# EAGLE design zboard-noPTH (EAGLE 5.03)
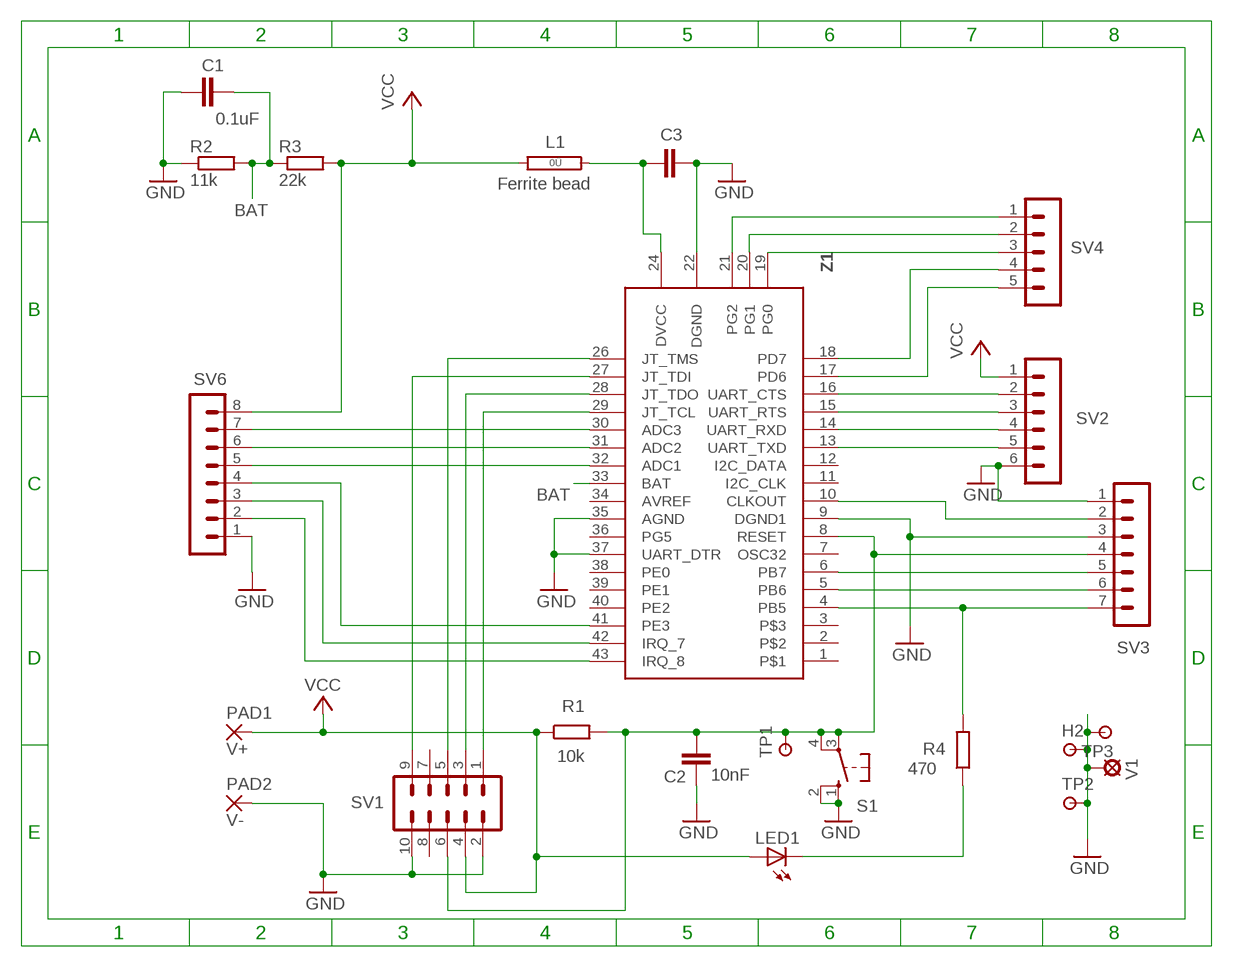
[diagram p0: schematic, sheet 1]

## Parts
C1  0.1uF  C5P  [C050-030-075]
C2  10nF  C5P  [C050-030-075]
C3  10uF 10V ceramic  CSMT0805  [C0805]
H2  HOLE/SMALL  [1,6/0,8@1]
L1  Ferrite bead  0R  [0R/10]
LED1  3mm red LED  LED-3MM3MM  [HLMP-D105]
PAD1  V+  TERMINAL-PAD  [2,54/1,1]
PAD2  V-  TERMINAL-PAD  [2,54/1,1]
R1  10k  R  [0207/10]
R2  11k  R  [0207/10]
R3  22k  R  [0207/10]
R4  470  R  [0207/10]
S1  BW-1000 PCB pushbutton  10-XX  [B3F-10XX]
SV1  10 way IDC male header  ML10  [ML10]
SV2  6 way pin header  MA06-1  [MA06-1]
SV3  7 way pin header  MA07-1  [MA07-1]
SV4  5 way pin header  MA05-1  [MA05-1]
SV6  6 way pin header  MA08-1  [MA08-1]
TP1  PAD-TESTPOINT  [1,6/0,8]
TP2  PAD-TESTPOINT  [1,6/0,8]
TP3  PAD-TESTPOINT  [1,6/0,8]
V1  HOLE/VIA  [LSP10]
Z1  ZDM-A1281-A2N  [ZIGSMD]

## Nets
BAT: C1.2 R2.2 R3.1 Z1.33(BAT)
GND: C1.1 C2.1 C3.2 H2.1(P) PAD2.1(P) R2.1 S1.1(S) S1.2(S1) SV1.2 SV1.10 SV2.6 SV3.1 SV3.3 SV6.1 TP2.1(P) TP3.1(P) V1.MP Z1.9(DGND1) Z1.22(DGND) Z1.35(AGND) Z1.37(UART_DTR)
N$1: SV4.4 Z1.18(PD7)
N$2: SV6.4 Z1.41(PE3)
N$3: SV2.2 Z1.16(UART_CTS)
N$4: SV6.7 Z1.30(ADC3)
N$5: SV6.6 Z1.31(ADC2)
N$7: SV6.5 Z1.32(ADC1)
N$8: SV4.5 Z1.17(PD6)
N$9: SV1.5 Z1.26(JT_TMS)
N$10: SV1.1 Z1.29(JT_TCL)
N$11: SV1.3 Z1.28(JT_TDO)
N$12: SV6.3 Z1.42(IRQ_7)
N$13: C2.2 R1.2 S1.3(P) S1.4(P1) SV1.6 SV3.4 TP1.1(P) Z1.8(RESET)
N$14: SV6.2 Z1.43(IRQ_8)
N$15: SV2.3 Z1.15(UART_RTS)
N$16: SV2.4 Z1.14(UART_RXD)
N$17: SV2.5 Z1.13(UART_TXD)
N$18: SV3.5 Z1.6(PB7)
N$19: SV3.6 Z1.5(PB6)
N$20: SV3.2 Z1.10(CLKOUT)
N$24: SV4.3 Z1.19(PG0)
N$25: SV4.2 Z1.20(PG1)
N$28: R4.2 SV3.7 Z1.4(PB5)
N$29: SV4.1 Z1.21(PG2)
N$30: LED1.K(C) R4.1
N$31: SV1.9 Z1.27(JT_TDI)
N$33 [supply]: C3.1 L1.1 Z1.24(DVCC)
VCC: L1.2 LED1.A PAD1.1(P) R1.1 R3.2 SV1.4 SV2.1 SV6.8
Unconnected: SV1.7 SV1.8 Z1.1 Z1.2 Z1.3 Z1.7(OSC32) Z1.11(I2C_CLK) Z1.12(I2C_DATA) Z1.34(AVREF) Z1.36(PG5) Z1.38(PE0) Z1.39(PE1) Z1.40(PE2)

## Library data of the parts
C1-C3 = ee2parts:C: Capacitor
H2 = ee2parts:HOLE/SMALL: SMALL THROUGH-HOLE PAD/TESTPOINT
L1 = jumper:0R: Bridge 0R 10mm
LED1 = ee2parts:LED-3MM: LED
PAD1 PAD2 = ee2parts:TERMINAL-PAD: LARGE THROUGH-HOLE PAD
R1-R4 = ee2parts:R: Resistor
S1 = switch-omron:10-XX: OMRON SWITCH
SV1 = con-harting-ml:ML10: HARTING
SV2 = con-lstb:MA06-1: PIN HEADER
SV3 = con-lstb:MA07-1: PIN HEADER
SV4 = con-lstb:MA05-1: PIN HEADER
SV6 = con-lstb:MA08-1: PIN HEADER
TP1-TP3 = ee2parts:PAD-TESTPOINT: SMALL THROUGH-HOLE PAD/TESTPOINT
V1 = ee2parts:HOLE/VIA: FIXED VIA
Z1 = ee2parts:ZDM-A1281-A2

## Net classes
1 supply: width 0.635 mm

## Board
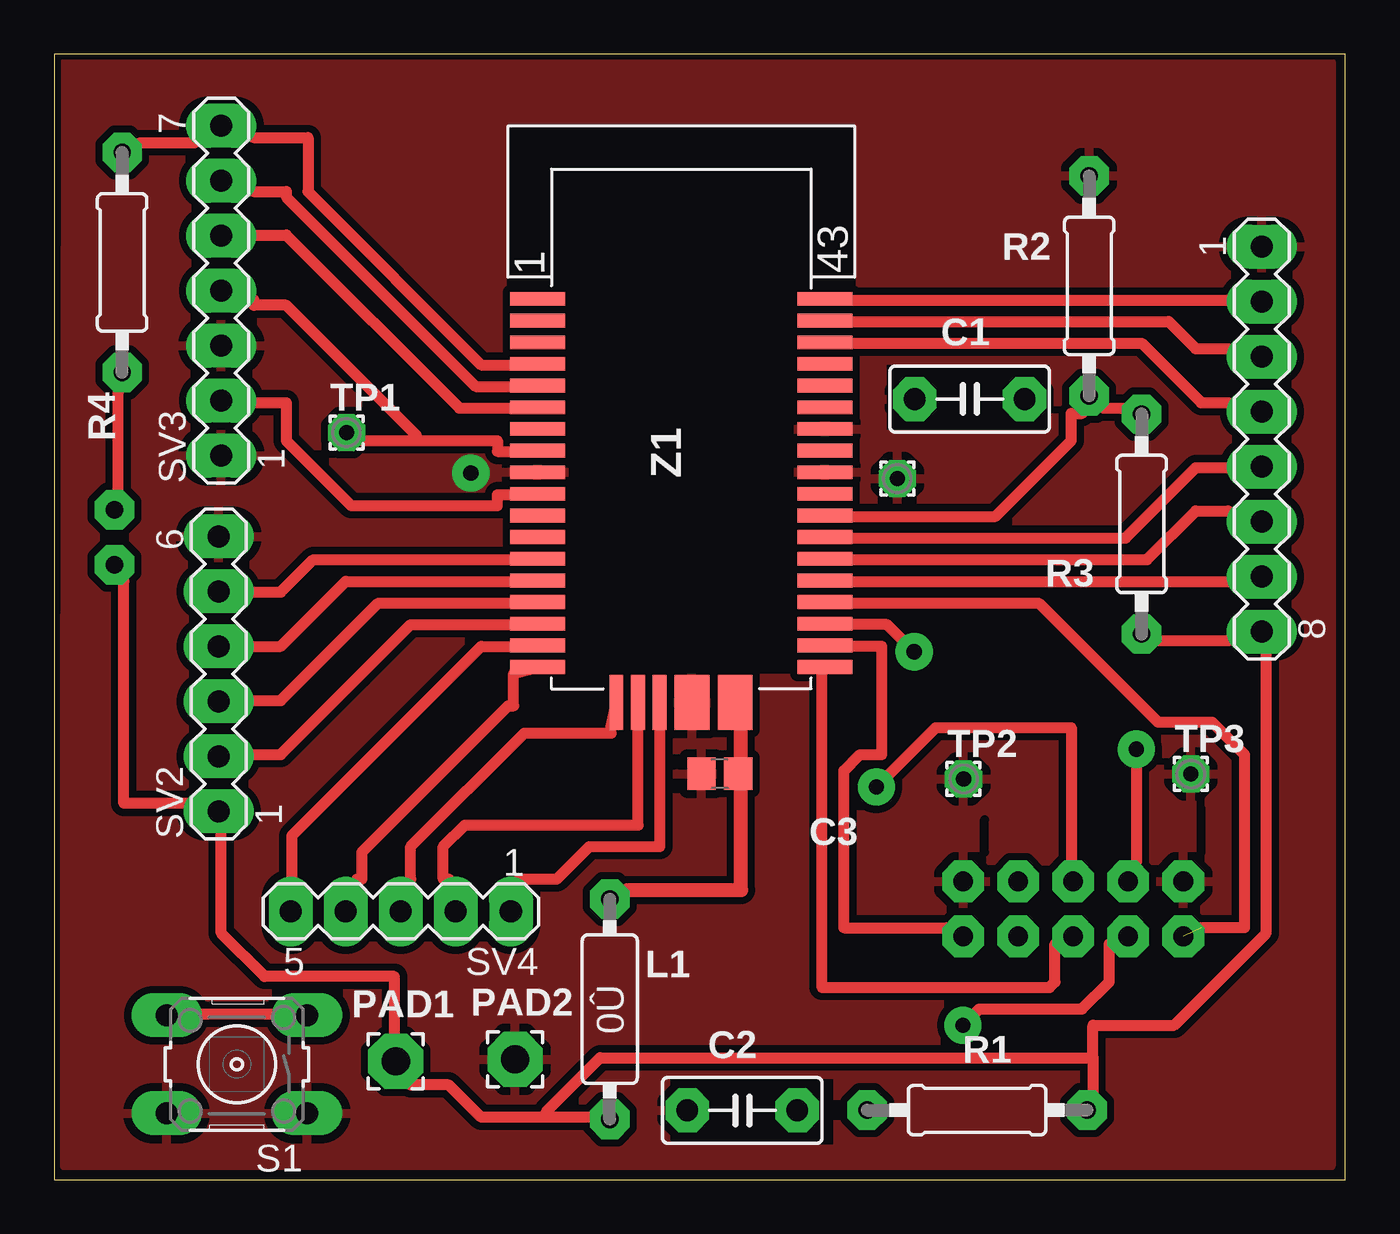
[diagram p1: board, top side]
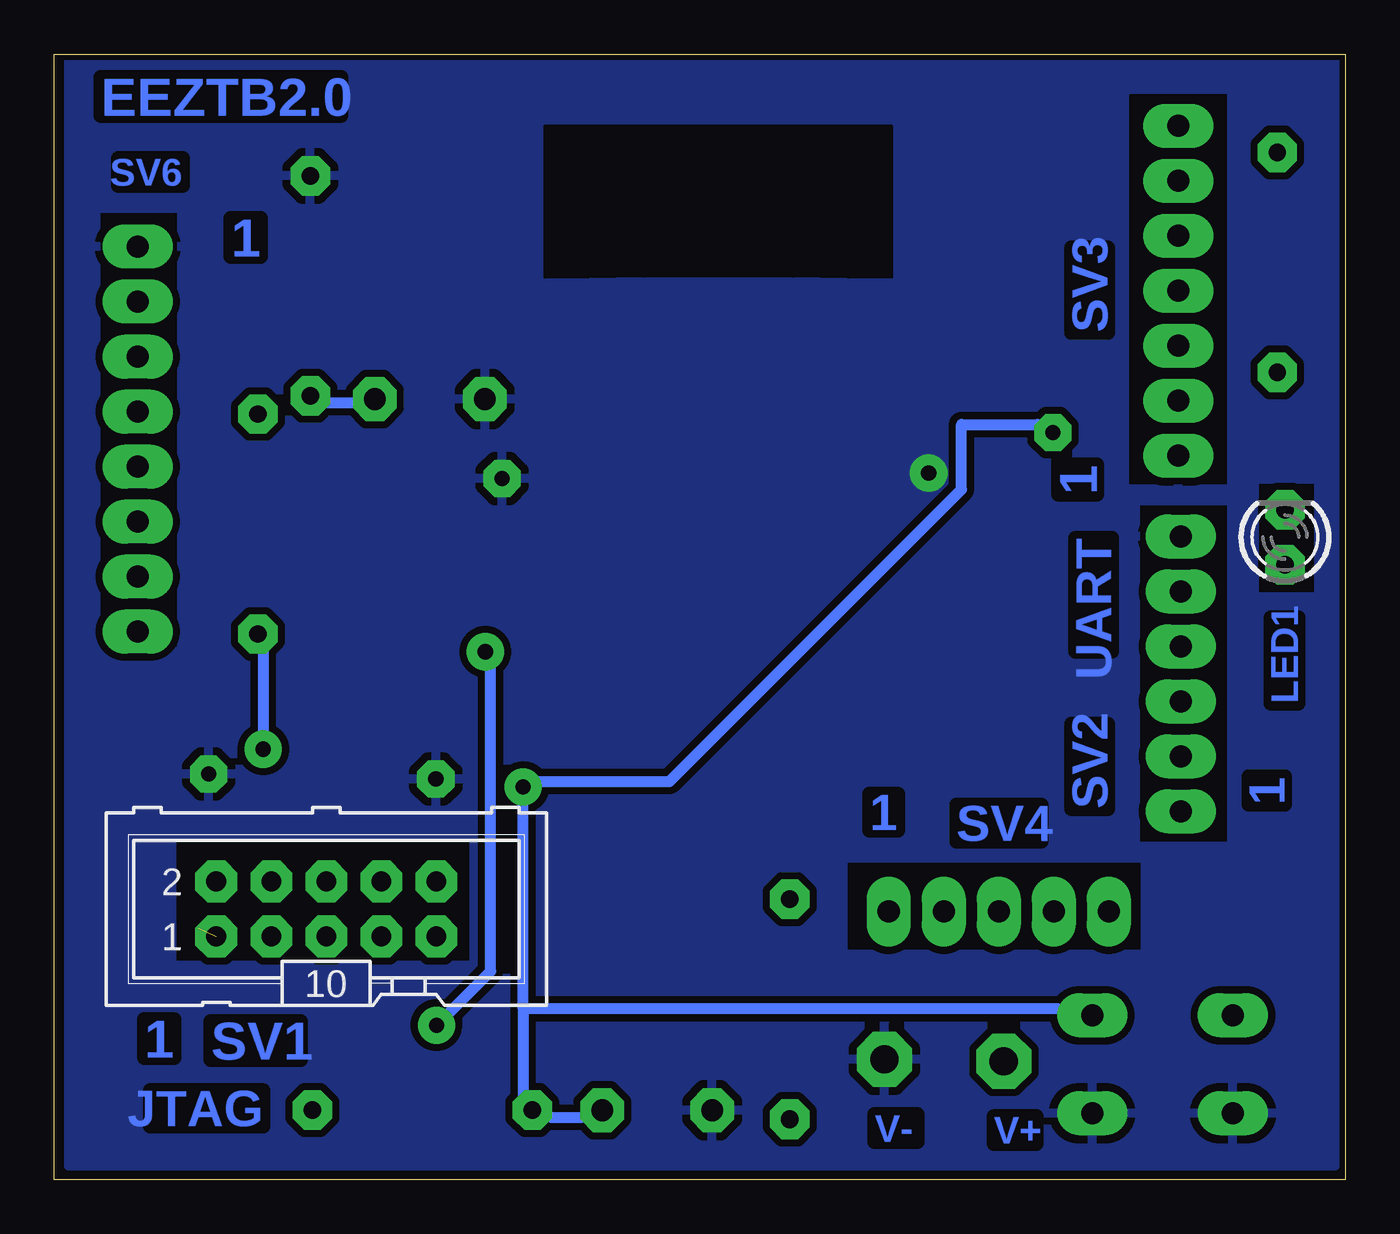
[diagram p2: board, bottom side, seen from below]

Size 59.63 x 51.98 mm. Coordinates in mm from the lower left corner, seen from the top.
Outline: 0,0 59.63,0 59.63,51.98 0,51.98 0,0
Copper layers (1*16): Top 0.035mm / dielectric 1.5mm / Bottom 0.035mm
Design rules "zigbit_rules *": minimum track width 20mil, minimum drill 0.7mm, track to track 13mil, track to pad 13mil, pad to pad 13mil, via to via 13mil, smd to smd 0mil, copper to edge 10mil, drill to drill 10mil, minimum pad ring 20mil, minimum via ring 20mil, stop-mask expansion 0mil, vias tented up to drill 0mil, thermal gap 15mil
tRestrict: area 38.5,34.6 to 46,37.6; area 28.5,1.6 to 36,4.6; 2 lines
bRestrict: area 54,24.6 to 57.5,44.6; area 5.5,32.1 to 10,50.1; area 40.5,10.1 to 54,15.6; area 1.5,27.1 to 4,32.1; area 5.5,15.6 to 9.5,31.1; area 9.5,10.6 to 23,14.6
vRestrict: area 37,8.1 to 57,17.1

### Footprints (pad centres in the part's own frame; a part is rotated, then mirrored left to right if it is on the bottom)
C050-030-075 = drill 1 octagon: 1 -2.54,0; 2 2.54,0
C0805 = smd 1.3 x 1.5: 1 -0.85,0; 2 0.85,0
1,6/0,8@1 = drill 0.7 pad 1.6 octagon: 1 0,0
0R/10 = drill 0.813 pad 1.6 octagon: 1 -5.08,0; 2 5.08,0
HLMP-D105 = drill 0.8 octagon: A -1.27,0; K 1.27,0
2,54/1,1 = drill 1.3 pad 2.54 octagon: 1 0,0
0207/10 = drill 0.8 octagon: 1 -5.08,0; 2 5.08,0
B3F-10XX = drill 1.016 long: 1 -3.251,2.261; 2 3.251,2.261; 3 -3.251,-2.261; 4 3.251,-2.261
ML10 = drill 0.914 octagon: 1 -5.08,-1.27; 2 -5.08,1.27; 3 -2.54,-1.27; 4 -2.54,1.27; 5 0,-1.27; 6 0,1.27; 7 2.54,-1.27; 8 2.54,1.27; 9 5.08,-1.27; 10 5.08,1.27
MA06-1 = drill 1.016 long: 1 -6.35,0; 2 -3.81,0; 3 -1.27,0; 4 1.27,0; 5 3.81,0; 6 6.35,0
MA07-1 = drill 1.016 long: 1 -7.62,0; 2 -5.08,0; 3 -2.54,0; 4 0,0; 5 2.54,0; 6 5.08,0; 7 7.62,0
MA05-1 = drill 1.016 long: 1 -5.08,0; 2 -2.54,0; 3 0,0; 4 2.54,0; 5 5.08,0
MA08-1 = drill 1.016 long: 1 -8.89,0; 2 -6.35,0; 3 -3.81,0; 4 -1.27,0; 5 1.27,0; 6 3.81,0; 7 6.35,0; 8 8.89,0
1,6/0,8 = drill 0.7 pad 1.6 octagon: 1 0,0
LSP10 = drill 0.7 pad 1.016 round: MP 0,0
ZIGSMD = smd 0.635 x 2.54: 1 7,6.635; 2 6,6.635; 3 5,6.635; 4 4,6.635; 5 3,6.635; 6 2,6.635; 7 1,6.635; 8 0,6.635; 9 -1,6.635; 10 -2,6.635; 11 -3,6.635; 12 -4,6.635; 13 -5,6.635; 14 -6,6.635; 15 -7,6.635; 16 -8,6.635; 17 -9,6.635; 18 -10,6.635; 26 -10,-6.635; 27 -9,-6.635; 28 -8,-6.635; 29 -7,-6.635; 30 -6,-6.635; 31 -5,-6.635; 32 -4,-6.635; 33 -3,-6.635; 34 -2,-6.635; 35 -1,-6.635; 36 0,-6.635; 37 1,-6.635; 38 2,-6.635; 39 3,-6.635; 40 4,-6.635; 41 5,-6.635; 42 6,-6.635; 43 7,-6.635 | smd 2.54 x 0.635: 19 -11.635,3; 20 -11.635,2; 21 -11.635,1 | smd 2.54 x 1.6: 22 -11.635,-0.5; 24 -11.635,-2.5

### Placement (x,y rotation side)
C1  42.28,36.05 0 top
C2  31.78,3.2 0 top
C3  30.74,18.75 180 top
H2  38.94,32.39 0 top
L1  25.66,7.87 270 top
LED1  2.79,29.67 90 bottom
PAD1  15.78,5.47 0 top
PAD2  21.28,5.55 0 top
R1  42.62,3.21 180 top
R2  47.8,41.28 270 top
R3  50.22,30.28 270 top
R4  3.14,42.36 90 top
S1  8.44,5.33 180 top
SV1  47.06,12.5 0 bottom
SV2  7.6,23.36 90 top
SV3  7.72,41.05 90 top
SV4  16.01,12.38 180 top
SV6  55.77,34.2 270 top
TP1  13.5,34.5 0 top
TP2  42,18.5 0 top
TP3  52.5,18.73 0 top
V1  19.24,32.63 0 top
Z1  28.96,33.67 90 top

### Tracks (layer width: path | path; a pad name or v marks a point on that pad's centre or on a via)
BAT
  Top 0.508: Z1.33 36.72,30.63 43.47,30.63 46.97,34.13 46.97,35.38 47.47,35.38 R2.2 48.47,35.63 49.47,35.63 R3.1
  Bottom 0.508: C1.2 45.72,35.88 46.97,35.88 R2.2
GND
  pour Bottom: 0.47,51.63 58.97,51.63 58.97,0.63 0.47,0.63
  pour Top: 0.53,51.63 58.97,51.63 58.97,0.63 0.47,0.63
N$1
  Top 0.508: Z1.18 21.22,23.38 21.22,21.88 20.97,21.88 14.22,15.13 14.22,13.88 13.97,13.88 SV4.4
N$2
  Top 0.508: Z1.41 36.72,38.63 50.22,38.63 52.97,35.88 54.22,35.88 SV6.4
N$3
  Top 0.508: Z1.16 21.22,25.63 16.47,25.63 10.47,19.63 9.22,19.63 SV2.2
N$4
  Top 0.508: Z1.30 36.72,27.63 54.22,27.63 SV6.7
N$5
  Top 0.508: Z1.31 36.72,28.63 50.47,28.63 52.72,30.88 54.22,30.88 SV6.6
N$7
  Top 0.508: Z1.32 36.72,29.63 49.47,29.63 52.72,32.88 54.22,32.88 SV6.5
N$8
  Top 0.508: Z1.17 21.22,24.63 19.72,24.63 10.97,15.88 10.97,13.88 SV4.5
N$9
  Top 0.508: Z1.26 35.47,23.38 35.47,8.88 45.97,8.88 46.22,9.13 46.22,10.88 SV1.5
N$10  (1 unrouted)
  Top 0.508: 52.97,11.63 54.97,11.63 54.97,19.63 53.47,21.13 50.97,21.13 45.47,26.63 36.72,26.63 Z1.29
N$11  (via drill 0.7)
  Top 0.508: v39.72,24.38 38.47,25.63 36.72,25.63 Z1.28 | v41.97,7.13 42.72,7.88 47.47,7.88 48.72,9.13 48.72,10.88 SV1.3
  Bottom 0.508: v39.72,24.38 39.47,24.13 39.47,9.63 v41.97,7.13
N$12
  Top 0.508: Z1.42 36.72,39.63 51.47,39.63 52.72,38.38 54.22,38.38 SV6.3
N$13  (via drill 0.7)
  Top 0.508: 16.72,34.13 14.22,34.13 TP1.1 | 16.72,34.13 20.47,34.13 20.47,33.63 21.22,33.63 Z1.8 | SV3.4 9.22,40.63 9.22,40.38 10.72,40.38 16.72,34.38 16.72,34.13 | S1.4 6.72,7.63 10.22,7.63 S1.3 | v37.97,18.13 40.72,20.88 46.97,20.88 46.97,14.63 SV1.6
  Bottom 0.508: C2.2 35.22,2.88 36.72,2.88 R1.2 37.97,3.88 37.97,7.88 | 37.97,7.88 v37.97,18.13 37.22,18.38 31.22,18.38 17.72,31.88 17.72,34.88 14.22,34.88 TP1.1 | S1.3 13.22,7.88 37.97,7.88
N$14
  Top 0.508: Z1.43 36.72,40.63 54.22,40.63 SV6.2
N$15
  Top 0.508: Z1.15 21.22,26.63 14.97,26.63 10.47,22.13 9.22,22.13 SV2.3
N$16
  Top 0.508: Z1.14 21.22,27.63 13.47,27.63 10.47,24.63 SV2.4
N$17
  Top 0.508: Z1.13 21.22,28.63 11.97,28.63 10.47,27.13 9.22,27.13 SV2.5
N$18
  Top 0.508: Z1.6 21.22,35.63 18.72,35.63 10.72,43.63 9.22,43.63 SV3.5
N$19
  Top 0.508: Z1.5 21.22,36.63 19.47,36.63 10.72,45.38 10.72,45.63 9.22,45.63 SV3.6
N$20
  Top 0.508: Z1.10 21.22,31.63 20.47,31.63 20.47,31.13 13.72,31.13 10.72,34.13 10.72,35.88 9.22,35.88 SV3.2
N$24
  Top 0.508: Z1.19 25.72,20.88 25.72,20.63 21.72,20.63 16.47,15.38 16.47,13.88 SV4.3
N$25
  Top 0.508: Z1.20 26.97,20.88 26.97,16.38 18.97,16.38 17.97,15.38 17.97,13.88 18.22,13.88 SV4.2
N$28
  Top 0.508: Z1.4 21.22,37.63 19.72,37.63 11.72,45.63 11.72,48.13 9.22,48.13 SV3.7 6.47,47.88 3.97,47.88 R4.2
N$29
  Top 0.508: Z1.21 27.97,20.88 27.97,15.38 24.72,15.38 23.22,13.88 21.47,13.88 SV4.1
N$30
  Top 0.508: LED1.K 2.97,31.63 2.97,36.38 R4.1
N$31
  Top 0.508: Z1.27 36.72,24.63 38.22,24.63 38.22,19.63 37.22,19.63 36.47,18.88 36.47,11.63 41.22,11.63 SV1.9
N$33
  Top 0.635: Z1.24 31.72,20.88 31.72,19.38 C3.1 31.72,18.13 31.72,13.38 26.47,13.38 L1.1
VCC  (via drill 0.7)
  Top 0.508: 47.97,5.63 47.97,7.13 51.72,7.13 55.97,11.38 55.97,24.38 SV6.8 54.22,24.88 50.97,24.88 R3.2 | 47.97,5.63 47.97,3.88 R1.1 | v49.97,19.88 49.97,14.63 SV1.4 | 22.72,2.88 19.72,2.88 18.22,4.38 16.47,4.38 PAD1.1 15.72,6.63 15.72,9.38 9.72,9.38 7.72,11.38 7.72,16.13 SV2.1 6.22,17.38 3.22,17.38 3.22,27.63 LED1.A | 22.72,2.88 24.97,2.88 L1.2 | 47.97,5.63 25.22,5.63 22.72,3.13 22.72,2.88
  Bottom 0.508: v49.97,19.88 49.97,24.38 R3.2

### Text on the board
Bottom: EEZTB2.0 | 1 | SV3 | 1 | UART | 1 | SV2 | SV4 | 1 | 1 | JTAG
